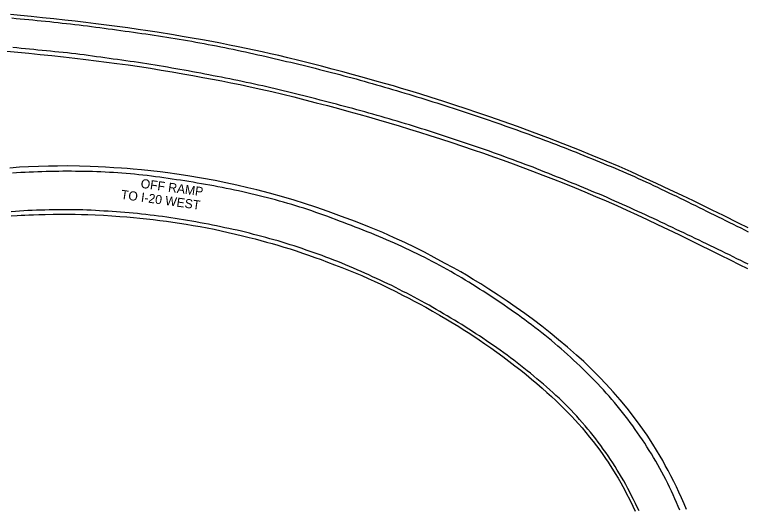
# Model space of a CAD drawing. Extents: x 1948091 to 1975253, y 787267 to 823306.
# Drawn here: x 1966519.3 to 1966953, y 802183.8 to 802477.2 of the extents above; entities that cross this region are included whole.
import ezdxf

# ---------------------------------------------------------------- set-up
doc = ezdxf.new("R2010")
doc.units = 0
for name, color, linetype in [('RD_EX_Pavement_Markings', 7, 'Continuous'), ('RD_EX_Road', 7, 'Continuous'), ('RD_TX_RoadID', 7, 'Continuous')]:
    doc.layers.add(name, color=color, linetype=linetype)

msp = doc.modelspace()

# ---------------------------------------------------------------- linework, layer by layer
at = {"layer": 'RD_EX_Pavement_Markings'}
for points in [[(1966517.68, 802475.24), (1966520.17, 802475.01), (1966522.66, 802474.78), (1966525.15, 802474.54), (1966527.64, 802474.3), (1966530.13, 802474.06), (1966532.61, 802473.82), (1966535.1, 802473.58), (1966537.59, 802473.33), (1966540.07, 802473.07), (1966542.56, 802472.8), (1966545.05, 802472.53), (1966547.53, 802472.26), (1966550.02, 802471.99), (1966552.5, 802471.73), (1966554.98, 802471.44), (1966557.46, 802471.12), (1966559.94, 802470.81), (1966562.42, 802470.5), (1966564.9, 802470.19), (1966567.38, 802469.87), (1966569.86, 802469.54), (1966572.34, 802469.21), (1966574.82, 802468.88), (1966577.3, 802468.55), (1966579.77, 802468.21), (1966582.25, 802467.86), (1966584.72, 802467.51), (1966587.2, 802467.17), (1966589.67, 802466.82), (1966592.15, 802466.47), (1966594.63, 802466.13), (1966597.1, 802465.77), (1966599.57, 802465.41), (1966602.05, 802465.04), (1966604.52, 802464.68), (1966606.99, 802464.32), (1966609.46, 802463.93), (1966611.93, 802463.52), (1966614.4, 802463.12), (1966616.86, 802462.71), (1966619.33, 802462.3), (1966621.79, 802461.86), (1966624.25, 802461.41), (1966626.71, 802460.95), (1966629.16, 802460.49), (1966631.62, 802460.03), (1966634.08, 802459.57), (1966636.53, 802459.1), (1966638.99, 802458.63), (1966641.44, 802458.15), (1966643.9, 802457.68), (1966646.35, 802457.17), (1966648.79, 802456.65), (1966651.23, 802456.13), (1966653.68, 802455.6), (1966656.12, 802455.08), (1966658.57, 802454.56), (1966661.01, 802454.01), (1966663.45, 802453.46), (1966665.88, 802452.91), (1966668.32, 802452.35), (1966670.76, 802451.8), (1966673.2, 802451.25), (1966675.63, 802450.68), (1966678.07, 802450.1), (1966680.5, 802449.52), (1966682.93, 802448.94), (1966685.36, 802448.37), (1966687.79, 802447.79), (1966690.23, 802447.21), (1966692.66, 802446.63), (1966695.08, 802446.01), (1966697.5, 802445.38), (1966699.92, 802444.76), (1966702.34, 802444.14), (1966704.76, 802443.52), (1966707.19, 802442.89), (1966709.61, 802442.27), (1966712.03, 802441.64), (1966714.45, 802441.02), (1966716.87, 802440.39), (1966719.29, 802439.77), (1966721.69, 802439.08), (1966724.1, 802438.39), (1966726.5, 802437.71), (1966728.9, 802437.02), (1966731.31, 802436.34), (1966733.71, 802435.65), (1966736.11, 802434.96), (1966738.52, 802434.27), (1966740.92, 802433.58), (1966743.32, 802432.86), (1966745.71, 802432.14), (1966748.1, 802431.42), (1966750.49, 802430.69), (1966752.89, 802429.97), (1966755.28, 802429.24), (1966757.67, 802428.51), (1966760.06, 802427.78), (1966762.45, 802427.06), (1966764.84, 802426.33), (1966767.23, 802425.57), (1966769.61, 802424.82), (1966772, 802424.07), (1966774.38, 802423.31), (1966776.76, 802422.56), (1966779.14, 802421.79), (1966781.52, 802421.02), (1966783.9, 802420.24), (1966786.27, 802419.46), (1966788.65, 802418.68), (1966791.01, 802417.87), (1966793.38, 802417.07), (1966795.74, 802416.26), (1966798.11, 802415.45), (1966800.48, 802414.65), (1966802.84, 802413.82), (1966805.2, 802413), (1966807.56, 802412.17), (1966809.92, 802411.34), (1966812.27, 802410.52), (1966814.63, 802409.69), (1966816.98, 802408.83), (1966819.33, 802407.98), (1966821.68, 802407.12), (1966824.03, 802406.26), (1966826.37, 802405.4), (1966828.72, 802404.53), (1966831.06, 802403.66), (1966833.41, 802402.79), (1966835.75, 802401.92), (1966838.08, 802401.03), (1966840.42, 802400.13), (1966842.75, 802399.23), (1966845.08, 802398.33), (1966847.41, 802397.43), (1966849.74, 802396.5), (1966852.06, 802395.57), (1966854.37, 802394.64), (1966856.69, 802393.7), (1966859.01, 802392.77), (1966861.33, 802391.83), (1966863.65, 802390.89), (1966865.96, 802389.95), (1966868.27, 802388.99), (1966870.58, 802388.02), (1966872.88, 802387.05), (1966875.18, 802386.08), (1966877.48, 802385.1), (1966879.78, 802384.11), (1966882.07, 802383.12), (1966884.37, 802382.13), (1966886.67, 802381.14), (1966888.94, 802380.11), (1966891.22, 802379.07), (1966893.49, 802378.04), (1966895.77, 802377), (1966898.03, 802375.93), (1966900.28, 802374.85), (1966902.54, 802373.77), (1966904.79, 802372.69), (1966907.05, 802371.61), (1966909.3, 802370.53), (1966911.55, 802369.45), (1966913.81, 802368.37), (1966916.06, 802367.29), (1966918.32, 802366.2), (1966920.55, 802365.09), (1966922.79, 802363.97), (1966925.03, 802362.86), (1966927.26, 802361.74), (1966929.5, 802360.63), (1966931.74, 802359.51), (1966933.98, 802358.4), (1966936.22, 802357.3), (1966938.47, 802356.2), (1966940.71, 802355.1), (1966942.96, 802354), (1966945.2, 802352.89), (1966947.45, 802351.79), (1966949.69, 802350.69), (1966951.93, 802349.59), (1966954.17, 802348.48)], [(1966954.15, 802329.12), (1966951.91, 802330.23), (1966949.67, 802331.34), (1966947.43, 802332.45), (1966945.19, 802333.55), (1966942.95, 802334.65), (1966940.7, 802335.76), (1966938.46, 802336.86), (1966936.22, 802337.96), (1966933.97, 802339.07), (1966931.72, 802340.16), (1966929.47, 802341.24), (1966927.21, 802342.31), (1966924.96, 802343.39), (1966922.7, 802344.47), (1966920.44, 802345.55), (1966918.19, 802346.63), (1966915.93, 802347.7), (1966913.68, 802348.78), (1966911.42, 802349.86), (1966909.17, 802350.94), (1966906.91, 802352.01), (1966904.65, 802353.09), (1966902.4, 802354.17), (1966900.14, 802355.25), (1966897.89, 802356.32), (1966895.61, 802357.37), (1966893.34, 802358.4), (1966891.07, 802359.44), (1966888.79, 802360.48), (1966886.52, 802361.52), (1966884.24, 802362.55), (1966881.97, 802363.59), (1966879.68, 802364.61), (1966877.4, 802365.62), (1966875.11, 802366.63), (1966872.83, 802367.64), (1966870.54, 802368.66), (1966868.25, 802369.67), (1966865.95, 802370.64), (1966863.64, 802371.6), (1966861.33, 802372.55), (1966859.02, 802373.51), (1966856.71, 802374.46), (1966854.4, 802375.42), (1966852.09, 802376.37), (1966849.77, 802377.31), (1966847.46, 802378.26), (1966845.15, 802379.21), (1966842.83, 802380.16), (1966840.52, 802381.1), (1966838.2, 802382.03), (1966835.88, 802382.96), (1966833.55, 802383.88), (1966831.23, 802384.81), (1966828.91, 802385.73), (1966826.59, 802386.66), (1966824.24, 802387.53), (1966821.9, 802388.4), (1966819.55, 802389.27), (1966817.21, 802390.13), (1966814.87, 802391), (1966812.52, 802391.87), (1966810.18, 802392.74), (1966807.83, 802393.61), (1966805.49, 802394.47), (1966803.14, 802395.34), (1966800.79, 802396.18), (1966798.43, 802397), (1966796.07, 802397.83), (1966793.71, 802398.65), (1966791.35, 802399.48), (1966788.98, 802400.29), (1966786.61, 802401.07), (1966784.23, 802401.85), (1966781.86, 802402.63), (1966779.48, 802403.4), (1966777.11, 802404.18), (1966774.73, 802404.96), (1966772.35, 802405.73), (1966769.97, 802406.5), (1966767.6, 802407.28), (1966765.22, 802408.05), (1966762.84, 802408.81), (1966760.45, 802409.55), (1966758.06, 802410.3), (1966755.68, 802411.04), (1966753.29, 802411.78), (1966750.9, 802412.51), (1966748.5, 802413.22), (1966746.11, 802413.94), (1966743.71, 802414.65), (1966741.31, 802415.36), (1966738.92, 802416.07), (1966736.51, 802416.76), (1966734.11, 802417.45), (1966731.71, 802418.14), (1966729.3, 802418.82), (1966726.9, 802419.51), (1966724.49, 802420.19), (1966722.08, 802420.85), (1966719.67, 802421.49), (1966717.25, 802422.14), (1966714.83, 802422.78), (1966712.42, 802423.42), (1966710, 802424.07), (1966707.58, 802424.7), (1966705.17, 802425.33), (1966702.75, 802425.96), (1966700.33, 802426.59), (1966697.91, 802427.22), (1966695.49, 802427.85), (1966693.07, 802428.47), (1966690.64, 802429.08), (1966688.22, 802429.68), (1966685.79, 802430.28), (1966683.36, 802430.89), (1966680.94, 802431.49), (1966678.51, 802432.1), (1966676.08, 802432.66), (1966673.64, 802433.23), (1966671.21, 802433.8), (1966668.77, 802434.37), (1966666.34, 802434.93), (1966663.9, 802435.48), (1966661.46, 802436.01), (1966659.01, 802436.54), (1966656.57, 802437.06), (1966654.12, 802437.59), (1966651.68, 802438.12), (1966649.23, 802438.61), (1966646.78, 802439.09), (1966644.32, 802439.57), (1966641.87, 802440.04), (1966639.41, 802440.52), (1966636.96, 802441), (1966634.5, 802441.47), (1966632.05, 802441.94), (1966629.59, 802442.41), (1966627.14, 802442.88), (1966624.68, 802443.35), (1966622.23, 802443.82), (1966619.77, 802444.26), (1966617.3, 802444.69), (1966614.84, 802445.12), (1966612.38, 802445.54), (1966609.91, 802445.97), (1966607.45, 802446.37), (1966604.98, 802446.77), (1966602.51, 802447.17), (1966600.04, 802447.57), (1966597.58, 802447.98), (1966595.11, 802448.38), (1966592.64, 802448.78), (1966590.17, 802449.14), (1966587.69, 802449.49), (1966585.22, 802449.85), (1966582.74, 802450.2), (1966580.27, 802450.55), (1966577.79, 802450.91), (1966575.32, 802451.26), (1966572.84, 802451.61), (1966570.37, 802451.95), (1966567.89, 802452.29), (1966565.41, 802452.63), (1966562.94, 802452.98), (1966560.46, 802453.3), (1966557.98, 802453.61), (1966555.5, 802453.93), (1966553.02, 802454.24), (1966550.53, 802454.5), (1966548.04, 802454.76), (1966545.56, 802455.02), (1966543.07, 802455.26), (1966540.58, 802455.51), (1966538.1, 802455.75), (1966535.61, 802456), (1966533.12, 802456.24), (1966530.63, 802456.49), (1966528.14, 802456.73), (1966525.66, 802456.98), (1966523.17, 802457.22), (1966520.68, 802457.47), (1966518.19, 802457.72)], [(1966913.6, 802183.2), (1966912.65, 802185.51), (1966911.65, 802187.8), (1966910.66, 802190.09), (1966909.62, 802192.37), (1966908.59, 802194.64), (1966907.52, 802196.9), (1966906.43, 802199.15), (1966905.33, 802201.4), (1966904.16, 802203.6), (1966902.99, 802205.81), (1966901.75, 802207.98), (1966900.52, 802210.16), (1966899.27, 802212.32), (1966898.01, 802214.48), (1966896.75, 802216.64), (1966895.44, 802218.77), (1966894.12, 802220.89), (1966892.75, 802222.98), (1966891.38, 802225.07), (1966889.96, 802227.13), (1966888.54, 802229.19), (1966887.1, 802231.23), (1966885.66, 802233.27), (1966884.18, 802235.29), (1966882.69, 802237.3), (1966881.18, 802239.29), (1966879.63, 802241.25), (1966878.09, 802243.22), (1966876.5, 802245.15), (1966874.91, 802247.08), (1966873.29, 802248.98), (1966871.66, 802250.88), (1966870, 802252.75), (1966868.32, 802254.59), (1966866.63, 802256.44), (1966864.91, 802258.25), (1966863.18, 802260.05), (1966861.44, 802261.85), (1966859.66, 802263.61), (1966857.89, 802265.37), (1966856.09, 802267.1), (1966854.28, 802268.83), (1966852.48, 802270.56), (1966850.64, 802272.26), (1966848.8, 802273.95), (1966846.97, 802275.65), (1966845.1, 802277.32), (1966843.24, 802278.98), (1966841.35, 802280.62), (1966839.45, 802282.24), (1966837.54, 802283.86), (1966835.6, 802285.43), (1966833.66, 802287), (1966831.7, 802288.56), (1966829.72, 802290.09), (1966827.74, 802291.62), (1966825.76, 802293.13), (1966823.76, 802294.64), (1966821.77, 802296.15), (1966819.74, 802297.61), (1966817.71, 802299.07), (1966815.68, 802300.52), (1966813.63, 802301.96), (1966811.58, 802303.39), (1966809.53, 802304.82), (1966807.46, 802306.22), (1966805.38, 802307.61), (1966803.3, 802309), (1966801.21, 802310.37), (1966799.12, 802311.73), (1966797.02, 802313.1), (1966794.93, 802314.47), (1966792.82, 802315.8), (1966790.7, 802317.14), (1966788.58, 802318.46), (1966786.44, 802319.75), (1966784.3, 802321.04), (1966782.14, 802322.3), (1966779.97, 802323.55), (1966777.8, 802324.79), (1966775.62, 802326.01), (1966773.44, 802327.23), (1966771.26, 802328.45), (1966769.06, 802329.64), (1966766.84, 802330.8), (1966764.63, 802331.95), (1966762.4, 802333.1), (1966760.18, 802334.24), (1966757.93, 802335.34), (1966755.68, 802336.42), (1966753.42, 802337.49), (1966751.16, 802338.57), (1966748.9, 802339.63), (1966746.64, 802340.7), (1966744.38, 802341.76), (1966742.08, 802342.75), (1966739.79, 802343.74), (1966737.48, 802344.72), (1966735.17, 802345.67), (1966732.86, 802346.61), (1966730.55, 802347.56), (1966728.22, 802348.48), (1966725.89, 802349.4), (1966723.57, 802350.31), (1966721.24, 802351.22), (1966718.9, 802352.11), (1966716.57, 802353.01), (1966714.24, 802353.91), (1966711.9, 802354.81), (1966709.56, 802355.69), (1966707.22, 802356.57), (1966704.89, 802357.45), (1966702.53, 802358.29), (1966700.17, 802359.11), (1966697.81, 802359.93), (1966695.44, 802360.75), (1966693.08, 802361.56), (1966690.71, 802362.36), (1966688.33, 802363.11), (1966685.94, 802363.86), (1966683.55, 802364.58), (1966681.15, 802365.29), (1966678.76, 802366), (1966676.34, 802366.66), (1966673.93, 802367.31), (1966671.51, 802367.94), (1966669.09, 802368.57), (1966666.67, 802369.19), (1966664.24, 802369.79), (1966661.81, 802370.38), (1966659.38, 802370.97), (1966656.95, 802371.54), (1966654.51, 802372.09), (1966652.07, 802372.63), (1966649.63, 802373.15), (1966647.18, 802373.67), (1966644.73, 802374.18), (1966642.28, 802374.64), (1966639.82, 802375.11), (1966637.37, 802375.58), (1966634.91, 802376.03), (1966632.45, 802376.47), (1966629.98, 802376.9), (1966627.52, 802377.34), (1966625.06, 802377.76), (1966622.59, 802378.18), (1966620.13, 802378.59), (1966617.66, 802378.96), (1966615.18, 802379.33), (1966612.71, 802379.7), (1966610.24, 802380.06), (1966607.76, 802380.42), (1966605.29, 802380.77), (1966602.81, 802381.09), (1966600.33, 802381.41), (1966597.85, 802381.73), (1966595.37, 802382.01), (1966592.88, 802382.29), (1966590.39, 802382.52), (1966587.9, 802382.74), (1966585.41, 802382.95), (1966582.92, 802383.14), (1966580.43, 802383.33), (1966577.93, 802383.5), (1966575.44, 802383.64), (1966572.94, 802383.78), (1966570.45, 802383.9), (1966567.95, 802384), (1966565.45, 802384.11), (1966562.95, 802384.2), (1966560.45, 802384.22), (1966557.95, 802384.24), (1966555.45, 802384.27), (1966552.95, 802384.29), (1966550.45, 802384.31), (1966547.96, 802384.29), (1966545.46, 802384.25), (1966542.96, 802384.21), (1966540.46, 802384.15), (1966537.96, 802384.1), (1966535.46, 802384.03), (1966532.96, 802383.94), (1966530.46, 802383.84), (1966527.97, 802383.74), (1966525.47, 802383.63), (1966522.97, 802383.52), (1966520.48, 802383.39), (1966517.98, 802383.25)], [(1966889.41, 802182.81), (1966888.32, 802185.06), (1966887.23, 802187.31), (1966886.14, 802189.56), (1966885.02, 802191.79), (1966883.88, 802194.02), (1966882.72, 802196.23), (1966881.52, 802198.42), (1966880.31, 802200.61), (1966879.07, 802202.78), (1966877.79, 802204.93), (1966876.52, 802207.08), (1966875.24, 802209.23), (1966873.88, 802211.32), (1966872.52, 802213.42), (1966871.14, 802215.5), (1966869.67, 802217.52), (1966868.19, 802219.54), (1966866.72, 802221.56), (1966865.24, 802223.58), (1966863.73, 802225.57), (1966862.23, 802227.56), (1966860.65, 802229.51), (1966859.05, 802231.43), (1966857.43, 802233.33), (1966855.78, 802235.21), (1966854.13, 802237.09), (1966852.48, 802238.96), (1966850.82, 802240.83), (1966849.12, 802242.66), (1966847.37, 802244.45), (1966845.62, 802246.23), (1966843.8, 802247.95), (1966841.99, 802249.67), (1966840.17, 802251.39), (1966838.32, 802253.06), (1966836.46, 802254.73), (1966834.6, 802256.4), (1966832.71, 802258.04), (1966830.79, 802259.65), (1966828.88, 802261.26), (1966826.97, 802262.87), (1966825.04, 802264.46), (1966823.07, 802266), (1966821.1, 802267.54), (1966819.14, 802269.09), (1966817.17, 802270.63), (1966815.2, 802272.17), (1966813.24, 802273.72), (1966811.23, 802275.21), (1966809.2, 802276.67), (1966807.17, 802278.13), (1966805.14, 802279.58), (1966803.09, 802281.01), (1966801.02, 802282.42), (1966798.95, 802283.82), (1966796.89, 802285.23), (1966794.82, 802286.63), (1966792.71, 802287.98), (1966790.61, 802289.33), (1966788.5, 802290.68), (1966786.4, 802292.03), (1966784.29, 802293.37), (1966782.15, 802294.66), (1966780.01, 802295.96), (1966777.87, 802297.25), (1966775.73, 802298.55), (1966773.58, 802299.81), (1966771.41, 802301.07), (1966769.25, 802302.32), (1966767.09, 802303.58), (1966764.92, 802304.81), (1966762.72, 802306), (1966760.52, 802307.19), (1966758.32, 802308.39), (1966756.13, 802309.58), (1966753.92, 802310.76), (1966751.71, 802311.92), (1966749.49, 802313.08), (1966747.28, 802314.24), (1966745.05, 802315.37), (1966742.8, 802316.46), (1966740.55, 802317.55), (1966738.3, 802318.63), (1966736.05, 802319.72), (1966733.77, 802320.76), (1966731.49, 802321.79), (1966729.22, 802322.83), (1966726.94, 802323.86), (1966724.65, 802324.87), (1966722.36, 802325.86), (1966720.07, 802326.86), (1966717.78, 802327.86), (1966715.48, 802328.84), (1966713.17, 802329.79), (1966710.85, 802330.74), (1966708.54, 802331.68), (1966706.2, 802332.58), (1966703.85, 802333.43), (1966701.5, 802334.29), (1966699.15, 802335.14), (1966696.8, 802335.99), (1966694.44, 802336.8), (1966692.08, 802337.61), (1966689.71, 802338.43), (1966687.35, 802339.24), (1966684.97, 802340.01), (1966682.59, 802340.77), (1966680.21, 802341.53), (1966677.82, 802342.29), (1966675.42, 802342.97), (1966673.01, 802343.64), (1966670.6, 802344.31), (1966668.19, 802344.98), (1966665.78, 802345.64), (1966663.37, 802346.28), (1966660.94, 802346.89), (1966658.52, 802347.5), (1966656.1, 802348.12), (1966653.67, 802348.73), (1966651.23, 802349.28), (1966648.79, 802349.8), (1966646.34, 802350.33), (1966643.9, 802350.86), (1966641.46, 802351.38), (1966639.01, 802351.88), (1966636.56, 802352.37), (1966634.11, 802352.86), (1966631.65, 802353.35), (1966629.2, 802353.81), (1966626.74, 802354.26), (1966624.28, 802354.72), (1966621.81, 802355.13), (1966619.35, 802355.52), (1966616.88, 802355.92), (1966614.41, 802356.31), (1966611.94, 802356.7), (1966609.47, 802357.1), (1966607, 802357.48), (1966604.52, 802357.78), (1966602.04, 802358.07), (1966599.55, 802358.37), (1966597.07, 802358.65), (1966594.59, 802358.92), (1966592.1, 802359.19), (1966589.62, 802359.46), (1966587.13, 802359.71), (1966584.64, 802359.89), (1966582.14, 802360.07), (1966579.65, 802360.25), (1966577.16, 802360.43), (1966574.66, 802360.59), (1966572.17, 802360.74), (1966569.67, 802360.89), (1966567.18, 802361.04), (1966564.68, 802361.16), (1966562.18, 802361.26), (1966559.68, 802361.35), (1966557.19, 802361.43), (1966554.69, 802361.44), (1966552.19, 802361.45), (1966549.69, 802361.46), (1966547.19, 802361.47), (1966544.69, 802361.44), (1966542.19, 802361.41), (1966539.69, 802361.37), (1966537.19, 802361.34), (1966534.69, 802361.28), (1966532.19, 802361.17), (1966529.7, 802361.06), (1966527.2, 802360.95), (1966524.7, 802360.84), (1966522.21, 802360.67), (1966519.72, 802360.47), (1966517.23, 802360.27)]]:
    msp.add_lwpolyline(points, dxfattribs=at)
at = {"layer": 'RD_EX_Road'}
for points in [[(1966954.07, 802350.68), (1966948.34, 802353.55), (1966939.46, 802357.98), (1966932.83, 802361.27), (1966927.2, 802364.05), (1966921.6, 802366.76), (1966915.06, 802369.9), (1966907.74, 802373.37), (1966899.8, 802377.08), (1966891.9, 802380.71), (1966884.7, 802383.94), (1966877.56, 802387.06), (1966869.84, 802390.36), (1966861.66, 802393.76), (1966853.15, 802397.21), (1966844.35, 802400.67), (1966835.34, 802404.13), (1966826.27, 802407.53), (1966817.33, 802410.79), (1966808.81, 802413.84), (1966801.03, 802416.57), (1966793.82, 802419.06), (1966787.02, 802421.36), (1966780.26, 802423.59), (1966773.17, 802425.86), (1966766.12, 802428.08), (1966759.48, 802430.16), (1966753.53, 802432), (1966748.53, 802433.51), (1966743.79, 802434.91), (1966738.6, 802436.42), (1966732.89, 802438.04), (1966726.61, 802439.79), (1966720.12, 802441.57), (1966713.74, 802443.3), (1966707.47, 802444.97), (1966701.27, 802446.62), (1966694.83, 802448.29), (1966687.84, 802450.04), (1966681.21, 802451.66), (1966675.83, 802452.94), (1966671, 802454.05), (1966666.04, 802455.17), (1966656.48, 802457.22), (1966651.77, 802458.17), (1966646.67, 802459.19), (1966641.39, 802460.23), (1966636.14, 802461.22), (1966630.62, 802462.23), (1966624.54, 802463.31), (1966618.61, 802464.34), (1966613.52, 802465.2), (1966603.68, 802466.77), (1966598.29, 802467.59), (1966592.45, 802468.47), (1966586.31, 802469.36), (1966580.02, 802470.23), (1966573.71, 802471.06), (1966567.52, 802471.86), (1966561.4, 802472.62), (1966555.26, 802473.34), (1966548.98, 802474.04), (1966542.43, 802474.72), (1966535.75, 802475.39), (1966529.09, 802476.05), (1966522.7, 802476.68), (1966516.85, 802477.23)], [(1966514.66, 802455.57), (1966521.22, 802454.97), (1966527.75, 802454.34), (1966534.52, 802453.65), (1966541.41, 802452.91), (1966548.27, 802452.16), (1966554.98, 802451.39), (1966561.41, 802450.63), (1966567.63, 802449.87), (1966573.72, 802449.12), (1966579.93, 802448.31), (1966586.53, 802447.39), (1966593.24, 802446.4), (1966599.79, 802445.4), (1966606.24, 802444.37), (1966612.67, 802443.28), (1966618.95, 802442.19), (1966624.99, 802441.1), (1966630.85, 802440.02), (1966636.59, 802438.94), (1966642.15, 802437.87), (1966647.46, 802436.82), (1966652.9, 802435.7), (1966658.88, 802434.42), (1966665.2, 802433.03), (1966671.66, 802431.55), (1966678.2, 802430.02), (1966684.72, 802428.42), (1966691.33, 802426.75), (1966698.11, 802425), (1966704.84, 802423.23), (1966711.31, 802421.48), (1966717.47, 802419.78), (1966723.25, 802418.18), (1966728.98, 802416.57), (1966735.01, 802414.84), (1966741.17, 802413.03), (1966747.31, 802411.19), (1966753.36, 802409.34), (1966759.28, 802407.51), (1966765.34, 802405.6), (1966771.79, 802403.52), (1966778.37, 802401.36), (1966784.76, 802399.22), (1966791.02, 802397.1), (1966797.14, 802395.01), (1966803.13, 802392.92), (1966808.96, 802390.84), (1966814.71, 802388.75), (1966820.47, 802386.62), (1966826.33, 802384.42), (1966832.43, 802382.08), (1966838.64, 802379.66), (1966844.84, 802377.21), (1966851.07, 802374.7), (1966857.37, 802372.08), (1966863.7, 802369.39), (1966870, 802366.68), (1966876.2, 802363.97), (1966882.22, 802361.28), (1966888.21, 802358.55), (1966894.28, 802355.73), (1966900.44, 802352.81), (1966906.72, 802349.8), (1966913.05, 802346.74), (1966919.38, 802343.65), (1966925.65, 802340.57), (1966931.78, 802337.54), (1966937.72, 802334.59), (1966943.41, 802331.75), (1966948.75, 802329.09), (1966953.65, 802326.69)], [(1966917.61, 802183.64), (1966916.14, 802187.09), (1966914.62, 802190.52), (1966913.1, 802193.88), (1966911.57, 802197.13), (1966909.99, 802200.34), (1966908.31, 802203.64), (1966906.61, 802206.87), (1966904.98, 802209.87), (1966903.43, 802212.67), (1966901.9, 802215.37), (1966897.61, 802222.49), (1966894.18, 802227.8), (1966890.11, 802233.55), (1966886.09, 802238.94), (1966882.41, 802243.8), (1966878.31, 802248.72), (1966874.11, 802253.46), (1966869.96, 802258.01), (1966866.02, 802262.1), (1966861.17, 802267.02), (1966856.6, 802271.4), (1966852.31, 802275.22), (1966846.99, 802279.92), (1966841.75, 802284.34), (1966836.8, 802288.44), (1966831.75, 802292.44), (1966826.83, 802296.17), (1966821.66, 802299.94), (1966816.58, 802303.53), (1966811.24, 802307.17), (1966805.82, 802310.81), (1966800.43, 802314.35), (1966795.57, 802317.47), (1966791.17, 802320.21), (1966787.23, 802322.68), (1966783.82, 802324.73), (1966779.53, 802327.08), (1966774.14, 802329.88), (1966767.9, 802333.25), (1966762.16, 802336.27), (1966756.68, 802339.06), (1966750.53, 802342.01), (1966744.31, 802344.85), (1966737.47, 802347.98), (1966729.62, 802351.2), (1966721.32, 802354.42), (1966713.14, 802357.57), (1966705.08, 802360.54), (1966697.86, 802363.03), (1966691.03, 802365.29), (1966685.07, 802367.15), (1966678.8, 802369.01), (1966670.35, 802371.36), (1966662.84, 802373.27), (1966657.43, 802374.56), (1966650.93, 802376.02), (1966644.41, 802377.49), (1966638.06, 802378.82), (1966630, 802380.31), (1966621.9, 802381.69), (1966615.41, 802382.64), (1966610.08, 802383.33), (1966605.6, 802383.92), (1966599.95, 802384.59), (1966594.51, 802385.14), (1966589.49, 802385.57), (1966585.97, 802385.89), (1966582.67, 802386.14), (1966578.07, 802386.44), (1966573.25, 802386.69), (1966568.87, 802386.9), (1966563.97, 802387.08), (1966557.75, 802387.32), (1966550.8, 802387.45), (1966544.62, 802387.44), (1966539.33, 802387.33), (1966533.42, 802387.13), (1966527.57, 802386.91), (1966522.14, 802386.66), (1966516.45, 802386.21)], [(1966517.25, 802357.82), (1966520.76, 802358.08), (1966523.17, 802358.22), (1966525.24, 802358.31), (1966527.71, 802358.41), (1966530.53, 802358.52), (1966533.65, 802358.63), (1966537.39, 802358.73), (1966542.06, 802358.8), (1966546.93, 802358.84), (1966551.28, 802358.84), (1966555.23, 802358.8), (1966558.92, 802358.73), (1966562.75, 802358.6), (1966567.12, 802358.42), (1966571.89, 802358.19), (1966576.91, 802357.89), (1966581.72, 802357.56), (1966585.88, 802357.25), (1966589.7, 802356.92), (1966593.53, 802356.55), (1966597.4, 802356.14), (1966601.35, 802355.68), (1966605.32, 802355.17), (1966609.22, 802354.66), (1966613.09, 802354.12), (1966616.95, 802353.55), (1966620.92, 802352.92), (1966625.09, 802352.22), (1966629.32, 802351.47), (1966633.47, 802350.7), (1966637.57, 802349.89), (1966641.64, 802349.02), (1966645.8, 802348.08), (1966650.17, 802347.06), (1966654.44, 802346.04), (1966658.3, 802345.08), (1966661.89, 802344.16), (1966665.32, 802343.24), (1966668.65, 802342.33), (1966671.94, 802341.42), (1966675.3, 802340.46), (1966678.88, 802339.38), (1966682.55, 802338.22), (1966686.2, 802337.03), (1966689.85, 802335.81), (1966693.54, 802334.55), (1966697.23, 802333.25), (1966700.93, 802331.9), (1966704.78, 802330.46), (1966708.93, 802328.87), (1966713.17, 802327.24), (1966717.24, 802325.66), (1966721.2, 802324.07), (1966725.06, 802322.43), (1966728.81, 802320.78), (1966732.45, 802319.13), (1966736.31, 802317.33), (1966740.72, 802315.18), (1966745.21, 802312.95), (1966749.3, 802310.87), (1966752.95, 802308.99), (1966756.13, 802307.35), (1966759.34, 802305.66), (1966763.05, 802303.64), (1966767.07, 802301.39), (1966771.21, 802298.99), (1966774.97, 802296.79), (1966777.82, 802295.1), (1966780.2, 802293.66), (1966782.56, 802292.19), (1966785.13, 802290.55), (1966788.16, 802288.62), (1966791.41, 802286.5), (1966794.67, 802284.31), (1966798.02, 802282), (1966801.54, 802279.52), (1966805.13, 802276.96), (1966808.69, 802274.37), (1966812.25, 802271.73), (1966815.83, 802268.98), (1966819.3, 802266.26), (1966822.51, 802263.68), (1966825.63, 802261.09), (1966828.87, 802258.35), (1966832, 802255.63), (1966834.82, 802253.08), (1966837.45, 802250.65), (1966840.01, 802248.26), (1966842.45, 802245.92), (1966844.77, 802243.64), (1966847.03, 802241.35), (1966849.35, 802238.97), (1966851.59, 802236.62), (1966853.62, 802234.41), (1966855.65, 802232.09), (1966857.86, 802229.44), (1966860.1, 802226.67), (1966862.21, 802223.99), (1966864.2, 802221.38), (1966866.09, 802218.82), (1966867.87, 802216.34), (1966869.52, 802213.97), (1966871.02, 802211.74), (1966872.35, 802209.72), (1966873.71, 802207.57), (1966875.31, 802204.98), (1966876.98, 802202.21), (1966878.55, 802199.51), (1966879.8, 802197.27), (1966880.55, 802195.86), (1966881.48, 802194.18), (1966884.29, 802188.66), (1966887.13, 802182.66)]]:
    msp.add_lwpolyline(points, dxfattribs=at)

# ---------------------------------------------------------------- texts
at = {"layer": 'RD_TX_RoadID'}
for s, p in [('OFF RAMP', (1966593.75, 802374.55)), ('TO I-20 WEST', (1966582.02, 802368))]:
    msp.add_text(s, height=5.4, rotation=352.0802, dxfattribs=at).set_placement(p)

doc.saveas('drawing.dxf')
